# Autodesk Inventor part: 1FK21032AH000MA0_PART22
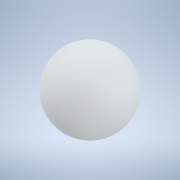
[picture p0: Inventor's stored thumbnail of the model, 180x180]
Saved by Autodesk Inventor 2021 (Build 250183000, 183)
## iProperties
Created: 2025-04
Part Number: 1FK21032AH000MA0_PART22
Material: Generic
Catalog Web Link: www.3dfindit.com
Description: -Servo synchronous motor
Document SubType Name: Modeling
Designer: psAdmin
Mass: 0.113097 g
Surface Area: 1.13097 cm^2
Volume: 0.113097 cm^3
Density: 1 g/cm^3
Appearance: PSOLRGB-212-217-219
Category: PARTsolutions
Title: 1FK21032AH000MA0_PART22
Author: Cadenas PARTsolutions
Comments: Servo synchronous motor
Sending System: PARTsolutions
Preprocessor: ST-DEVELOPER v19.3
PSOL_IDENT_0: {$CADENAS_DATA/23d-libs/siemens_ag/_cat_/45/10/1fk21032ah000ma0.prj},216 {VTYP=3D},{NB=1FK21032AH000
PSOL_IDENT_1: MA0_PART22},{LINA=1FK21032AH000MA0_PART22},{NN=1FK21032AH000MA0_PART22},{NOPRJ=TRUE},{DATE=19.08.202
PSOL_IDENT_2: 5 14:00:35},{GEOMDATE=30.07.2025 02:02:03},{VERSION=},{LINEID=10},{WBVAR=},{WBNUMERIC=}  {NB=1FK2103
PSOL_IDENT_3: 2AH000MA0_PART22},{LINA=1FK21032AH000MA0_PART22},{KT=DUMMY},{PREVIEW=../../../_pool_/14/8e/p_d211_xx
PSOL_IDENT_4: _00426j.png},{DESCSHORT=SIMOTICS S-1FK2 HD, SINAMICS S210 3AC 400V-480V, 0.59 Nm, 4500 rpm},{DESCLON
PSOL_IDENT_5: G=SIMOTICS S-1FK2 HD servo motor M0=0.64 Nm; PN = 0.28 kW at nN=4500 rpm (380-480 V); PN = 0.167 kW
PSOL_IDENT_6: at nN=2500 rpm (200-240 V); degree of protection IP64; cylindrical shaft D14 x 30 mm; absolute encod
PSOL_IDENT_7: er 22-bit + 12-bit multiturn (encoder AM22DQC); with OCC interface; plug size M17, rotatable; SIMOTI
PSOL_IDENT_8: CS S-1FK2 servomotorfor a wide range of uses in industrial environments. SIMOTICS S‑1FK2 servomotors
PSOL_IDENT_9: are compact synchronous motors with a high dynamic performance that set themselves apart as a resul
PSOL_IDENT_10: t of their high power density, degree of protection and overload capability. The motors are availabl
PSOL_IDENT_11: e in two variants: as High Dynamic variant (highest dynamic performance as a result of the low intri
PSOL_IDENT_12: nsic moment of inertia for applications demanding a high dynamic performance with low moved masses)
PSOL_IDENT_13: - and as Compact variant (precise and stable closed-loop control for medium up to large moved masses
PSOL_IDENT_14: as a result of a medium intrinsic moment of inertia). SIMOTICSS‑1FK2 servomotors fully exploit thei
PSOL_IDENT_15: r strengths in a system with the SINAMICSS210 frequency converter and simple connection using the on
PSOL_IDENT_16: e cable connection (OCC). Advantages include the short control and positioning times, fast and preci
PSOL_IDENT_17: se correction of disturbing quantities as well as stable control with a high dynamic performance. Th
PSOL_IDENT_18: e servo motors can be configured to address a wide range of requirements. For example with and witho
PSOL_IDENT_19: ut holding brake, IP64 or IP65 degree of protection, singleturn or multiturn absolute encoders - to
PSOL_IDENT_20: name just a few. Further, the servomotors are available in different shaft heights extending from 20
PSOL_IDENT_21: to 100. A shaft sealing ring is available to achieve an IP65 degree of protection and for subsequen
PSOL_IDENT_22: t mounting at the motor or as spare part. SIMOTICS - the optimum motor for each and every motion con
PSOL_IDENT_23: trol application.},{INTNO=195125335004},{SUPPLIERALTNO=1FK2103-2AH00-0MA0},{MANUID=1FK21032AH000MA0}
PSOL_IDENT_24: ,{MANUNAME=Siemens},{MANUTYPEDESC=SYNCHRONOUS MOTOR 1FK2 HD 0,64 NM},{AAU732=SIMOTICS},{AAO057=S-1FK
PSOL_IDENT_25: 2},{AAU734=SIMOTICS S-1FK2 HD servo motor M0=0.64 Nm; PN = 0.28 kW at nN=4500 rpm (380-480 V); PN =
PSOL_IDENT_26: 0.167 kW at nN=2500 rpm (200-240 V); degree of protection IP64; cylindrical shaft D14 x 30 mm; absol
PSOL_IDENT_27: ute encoder 22-bit + 12-bit multiturn (encoder AM22DQC); with OCC interface; plug size M17, rotatabl
PSOL_IDENT_28: e;},{AAW338=SYNCHRONOUS MOTOR 1FK2 HD 0,64 NM},{AAO742=SIMOTICS},{AAO663=4034106444624},{NOCUPEROU=1
PSOL_IDENT_29: },{PRICEQUANTITY=1},{QUANTITYMIN=1},{QUANTITYINT=1},{CTN=85015100},{COO=RO},{AAO676=1FK2103-2AH00-0M
PSOL_IDENT_30: A0},{AAO677=Siemens AG},{ORDERUNIT=C62},{CONTENTUNIT=C62}
NB: 1FK21032AH000MA0_PART22
NT: Servo synchronous motor
NBSYN: $MANUID._PART22
LINA: 1FK21032AH000MA0_PART22
CATALOG: SIEMENS
PREVIEW: ../../../_pool_/14/8e/p_d211_xx_00426j.png
DESCSHORT: SIMOTICS S-1FK2 HD, SINAMICS S210 3AC 400V-480V, 0.59 Nm, 4500 rpm
DESCLONG: SIMOTICS S-1FK2 HD servo motor M0=0.64 Nm; PN = 0.28 kW at nN=4500 rpm (380-480 V); PN = 0.167 kW at nN=2500 rpm (200-240 V); degree of protection IP64; cylindr
INTNO: 195125335004
SUPPLIERALTNO: 1FK2103-2AH00-0MA0
MANUID: 1FK21032AH000MA0
MANUNAME: Siemens
MANUTYPEDESC: SYNCHRONOUS MOTOR 1FK2 HD 0,64 NM
AAU732: SIMOTICS
AAO057: S-1FK2
AAU734: SIMOTICS S-1FK2 HD servo motor M0=0.64 Nm; PN = 0.28 kW at nN=4500 rpm (380-480 V); PN = 0.167 kW at nN=2500 rpm (200-240 V); degree of protection IP64; cylindr
AAW338: SYNCHRONOUS MOTOR 1FK2 HD 0,64 NM
AAO742: SIMOTICS
AAO663: 4034106444624.0
NOCUPEROU: 1
PRICEQUANTITY: 1
QUANTITYMIN: 1
QUANTITYINT: 1
CTN: 85015100
COO: RO
ARTICLENO: 1FK21032AH000MA0_PART22
BOMINFO: 1FK21032AH000MA0_PART22
CREATOR: CADENAS GmbH
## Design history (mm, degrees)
feature "2025_04_17_15_00_20_0760"
body "Solid1"
